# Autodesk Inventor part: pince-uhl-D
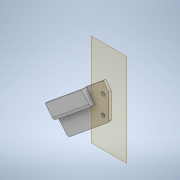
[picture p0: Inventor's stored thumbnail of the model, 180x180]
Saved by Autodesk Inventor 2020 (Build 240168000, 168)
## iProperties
Created: 2022-02
Part Number: pince-uhl-D
Material: Générique
Document SubType Name: Modeling
Designer: bruno
Density: 1 g/cm^3
Appearance: Par défaut
Author: bruno
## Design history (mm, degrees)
node "Plan de construction1"
sketch "Esquisse1"
  geometry: L1 (-5.15, 32.999)-(-17.137, 23.172); L2 (-17.137, 23.172)-(-70.014, -20.174); L3 (-0.176, -17.069)-(-0.176, 3.969) reference; L4 (-6.227, -22.088)-(0.143, -15.835) reference; L5 (-6.674, -23.391)-(-0.176, -17.069) reference; L6 (-9.751, 8.635)-(-13.148, 5.27) reference; L7 (-19.564, -3.887)-(-16.006, -8.227); L8 (-16.006, -8.227)-(-42.037, -29.566); L9 (-36.045, -47.468)-(-37.599, -45.572); L10 (-19.285, -1.073)-(-4.68, 10.901); L11 (-4.68, 10.901)-(-0.176, 5.407); L12 (-42.316, -32.381)-(-34.606, -41.786); L13 (-31.791, -42.065)-(-0.908, -16.748); L14 (-43.363, -30.653)-(-43.584, -30.834); L15 (-43.584, -30.834)-(-42.969, -31.584); L16 (-0.176, -15.201)-(-0.176, 5.407); C1 r 2.8 at (-17.137, 23.172) reference; C2 r 1.75 at (-5.15, 32.999) reference; C3 r 1.5 at (-4.674, 1.655) reference; C4 r 1.5 at (-4.68, -13.34) reference; A1 r 2 centre (-18.017, -2.619) between (-19.285, -1.073) and (-19.564, -3.887); A2 r 2 centre (-40.769, -31.113) between (-42.037, -29.566) and (-42.316, -32.381); A3 r 2 centre (-33.059, -40.518) between (-34.606, -41.786) and (-31.791, -42.065); A4 r 2 centre (-2.176, -15.201) between (-0.908, -16.748) and (-0.176, -15.201); 5 further points
  constraints: 24 end point, 10 point on line, 8 point on circle, 8 tangent, 4 centre point, 3 equal radius, 3 parallel, 2 collinear, 2 perpendicular, 1 vertical
  dimensions: "d1" = 25 distance between parallel lines of L2 L8; "d38" = 2 radius of A1 (derived)
extrude "Extrusion3" new body sketch "Esquisse1" distance "d10" = 2; taper "d11" = 0 deg
sketch "Esquisse11"
  geometry: L1 (0, 3.958)-(2, 3.958) reference; L2 (2, 9.612)-(0, 9.612) reference; L3 (0, 2)-(0, 0) reference; L4 (0, 2)-(0, 7.612) reference; L5 (2, 0)-(2, 2) reference; L6 (2, 7.612)-(2, 2) reference; L7 (2, 7.612)-(2, 9.612) reference; L8 (0, 9.612)-(0, 7.612) reference; L9 (2, 2)-(0, 2) reference; L10 (-4.52, 2)-(5.707, 2); L11 (5.707, 2)-(5.707, -1.785); L12 (5.707, -1.785)-(-4.52, -1.785); L13 (-4.52, -1.785)-(-4.52, 2); L14 (5.707, -1.785)-(3.366, -1.785); L15 (3.366, -1.785)-(3.366, 9.612); L16 (3.366, 9.612)-(5.707, 9.612); L17 (5.707, 9.612)-(5.707, -1.785); 5 further points
  constraints: 16 end point, 4 parallel, 2 horizontal, 2 perpendicular
extrude "Extrusion11" join sketch "Esquisse11" stored distance "d39" = 10; taper "d40" = 0 deg
sketch "Esquisse12"
  geometry: L1 (35.659, 11.397)-(35.659, 0) reference; L2 (0, 11.397)-(35.659, 11.397) reference; L3 (35.659, 11.397)-(38.659, 11.397); L4 (38.659, 11.397)-(38.659, 0); L5 (38.659, 0)-(35.659, 0); L6 (35.659, 0)-(35.659, 11.397); 2 further points
  constraints: 8 end point, 2 parallel, 1 horizontal, 1 perpendicular
  dimensions: "d41" = 3 distance of L4.end L5.end
extrude "Extrusion12" join sketch "Esquisse12" stored distance "d42" = 10; taper "d43" = 0 deg
fillet "Congé8" dims "d44" = 2
node "Solide2"
node "Référence1"
node "Référence2"
node "Référence3"
node "Référence4"
node "Référence5"
node "Référence6"
node "Référence7"
node "Référence8"
